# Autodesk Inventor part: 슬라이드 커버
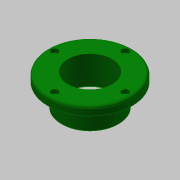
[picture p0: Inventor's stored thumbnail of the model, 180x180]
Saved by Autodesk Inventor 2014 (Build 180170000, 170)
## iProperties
Created: 2015-10
Part Number: 슬라이드 커버
Document SubType Name: Modeling
Designer: mdu
Density: 7.86 g/cm^3
Material: 알루미늄 6061
Mass: 598.523 g
Surface Area: 229.996 cm^2
Volume: 76.148 cm^3
Appearance: 진녹색
Author: mdu
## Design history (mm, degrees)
sketch "스케치1"
  geometry: C1 r 47.5 at (0, 0); C2 r 32.5 at (0, 0); 1 further point
  constraints: 2 centre point, 2 coincident
  dimensions: "d33" = 95 diameter of C1; "d35" = 65 diameter of C2
extrude "돌출1" new body sketch "스케치1" distance "d0" = 10; taper "d1" = 0 deg
extrude "돌출2" join sketch "스케치1" distance "d2" = 26; taper "d3" = 0 deg
hole "구멍1" diameter "d6" = 50; stored, may be unused: countersink angle "d10" = 90 deg, drill point angle "d12" = 118 deg; dims "d4" = 10, "d5" = 10, "d7" = 6, "d8" = 4, "d9" = 2, "d11" = 8
sketch "스케치2" dims "d36" = 80
  geometry: 4 further points
  constraints: 2 coincident, 2 vertical alignment, 2 other
hole "구멍2" sketch "스케치2" at (0, 40) diameter "d13" = 4.5; stored, may be unused: countersink angle "d17" = 90 deg, drill point angle "d19" = 118 deg; dims "d14" = 6, "d15" = 8, "d16" = 4.4, "d18" = 8
fillet "모깎기1" dims "d23" = 3
chamfer "모따기1" distance "d24" = 1; stored, may be unused: second distance "d25" = 2, angle "d26" = 45 deg
sketch "스케치3"
  geometry: C1 r 25 at (0, 0); C2 r 30 at (0, 0); C3 r 26 at (0, 0) reference; 1 further point
  constraints: 2 centre point, 2 coincident
  dimensions: "d27" = 60 diameter of C2
extrude "돌출3" cut sketch "스케치3" distance "d28" = 3; taper "d29" = 0 deg
chamfer "모따기2" distance "d30" = 1; stored, may be unused: second distance "d31" = 2, angle "d32" = 45 deg
node "솔리드1"
pattern_circular "원형 패턴1" dims angle "d21" = 360 deg
